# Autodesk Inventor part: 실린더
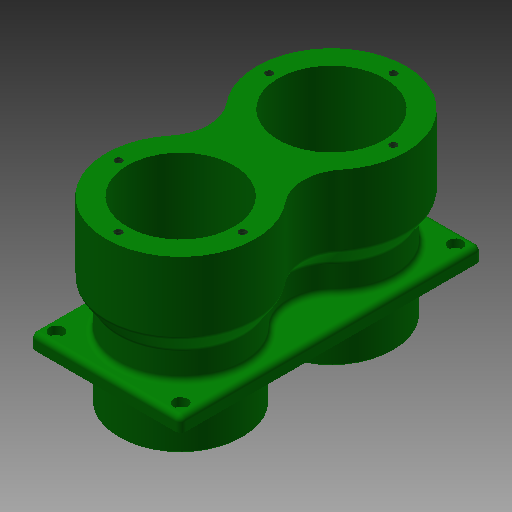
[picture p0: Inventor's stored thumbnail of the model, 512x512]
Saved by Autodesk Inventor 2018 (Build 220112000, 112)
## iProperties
Created: 2016-11
Part Number: 실린더
Material: 알루미늄 6061
Document SubType Name: Modeling
Designer: mduedu
Density: 2.71 g/cm^3
Mass: 1199.25 g
Surface Area: 1038.68 cm^2
Volume: 442.528 cm^3
Appearance: 진녹색
Author: mduedu
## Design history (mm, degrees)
sketch "스케치1"
  geometry: L1 (0, 0)-(0, 101); L2 (30, 0)-(30, 101); L3 (30, 101)-(42, 101); L4 (42, 101)-(42, 61); L5 (42, 61)-(35, 51); L6 (35, 51)-(35, 0); L7 (35, 0)-(30, 0)
  constraints: 14 end point, 4 parallel, 2 horizontal alignment, 1 perpendicular, 1 vertical
  dimensions: "d0" = 101 distance of L1.start L1.end; "d1" = 60 diameter of L2.end L1; "d2" = 84 diameter of L3.end L1; "d3" = 70 diameter of L6.end L1; "d4" = 40 distance of L3.end L4.end; "d5" = 50 vertical distance of L5.end L3.end
revolve "회전1" stored, may be unused: angle "d6" = 90 deg
node "작업 평면1"
sketch "스케치2"
  geometry: L1 (-42.5, -42.5)-(42.5, -42.5); L2 (42.5, -42.5)-(42.5, 42.5); L3 (42.5, 42.5)-(-42.5, 42.5); L4 (-42.5, 42.5)-(-42.5, -42.5); L5 (-42.5, -42.5)-(42.5, 42.5); L6 (42.5, -42.5)-(-42.5, 42.5); C1 r 35 at (0, 0) reference; C2 r 35 at (0, 0); 1 further point
  constraints: 12 end point, 2 midpoint, 2 parallel, 2 perpendicular, 1 centre point, 1 coincident, 1 concentric, 1 horizontal
  dimensions: "d8" = 85 distance of L2.end L3.end
extrude "돌출1" join sketch "스케치2" distance "d10" = 8; taper "d11" = 0 deg
chamfer "모따기1" distance "d14" = 1; stored, may be unused: second distance "d15" = 2, angle "d16" = 45 deg
chamfer "모따기2" distance "d17" = 5; stored, may be unused: second distance "d18" = 2, angle "d19" = 15 deg
sketch "스케치3"
  geometry: L1 (-35, -35)-(35, -35); L2 (35, -35)-(35, 35); L3 (35, 35)-(-35, 35); L4 (-35, 35)-(-35, -35); L5 (-35, -35)-(35, 35); L6 (35, -35)-(-35, 35); 3 further points
  constraints: 12 end point, 2 coincident, 2 midpoint, 2 parallel, 1 horizontal, 1 perpendicular
  dimensions: "d20" = 70 distance of L3.end L2.end; "d21" = 70 distance of L2.end L1.end
sketch "스케치4"
  geometry: 2 further points
  constraints: 2 other
hole "구멍1" sketch "스케치4" at (-35, 35), (35, 35) diameter "d22" = 4.5; stored, may be unused: countersink angle "d26" = 90 deg, drill point angle "d28" = 0 deg; dims "d23" = 6, "d24" = 8, "d25" = 4.6, "d27" = 8
sketch "스케치5"
  geometry: 3 further points
  constraints: 3 other
hole "구멍2" sketch "스케치5" at (35, 0), (-35, 0), (0, 35) diameter "d29" = 4.134; stored, may be unused: countersink angle "d33" = 90 deg, drill point angle "d35" = 120 deg; dims "d30" = 7.5, "d31" = 4, "d32" = 2, "d34" = 10
fillet "모깎기3" dims "d36" = 3
fillet "모깎기4" dims "d37" = 3
sketch "스케치6"
  geometry: L1 (0, 0)-(0, -85); A1 r 42 centre (0, 0) between (32.469, -26.642) and (-32.469, -26.642) reference; A2 r 42 centre (0, -85) between (32.469, -58.358) and (-32.469, -58.358) reference; A3 r 25 centre (51.795, -42.5) between (32.469, -58.358) and (32.469, -26.642); A4 r 25 centre (-51.795, -42.5) between (-32.469, -26.642) and (-32.469, -58.358); A5 r 25 centre (51.795, -42.5) between (32.469, -26.642) and (32.469, -58.358); A6 r 25 centre (-51.795, -42.5) between (-32.469, -58.358) and (-32.469, -26.642); A7 r 42 centre (0, 0) between (-32.469, -26.642) and (32.469, -26.642); A8 r 42 centre (0, -85) between (32.469, -58.358) and (-32.469, -58.358); A9 r 42 centre (0, 0) between (32.469, -26.642) and (-32.469, -26.642); A10 r 42 centre (0, -85) between (-32.469, -58.358) and (32.469, -58.358); 1 further point
  constraints: 20 point on circle, 8 centre point, 2 coincident, 2 end point, 2 tangent, 1 symmetric about line, 1 vertical, 1 other
  dimensions: "d38" = 50 diameter of A3
node "작업 평면2"
sketch "스케치7"
  geometry: A1 r 25 centre (9.795, -42.5) between (-9.531, -26.642) and (-9.531, -58.358) reference; A2 r 42 centre (-42, 0) between (-74.469, -26.642) and (-9.531, -26.642) reference; A3 r 42 centre (-42, -85) between (-9.531, -58.358) and (-74.469, -58.358) reference; A4 r 25 centre (-93.795, -42.5) between (-74.469, -58.358) and (-74.469, -26.642) reference; 1 further point
node "작업 평면3"
sketch "스케치8"
  geometry: L1 (-35, 0)-(-35, -85); A1 r 35 centre (-35, 0) between (-10.294, -24.792) and (-59.706, -24.792) reference; A2 r 35 centre (-35, -85) between (-10.294, -60.208) and (-59.706, -60.208) reference; A3 r 25 centre (7.353, -42.5) between (-10.294, -60.208) and (-10.294, -24.792); A4 r 25 centre (-77.353, -42.5) between (-59.706, -24.792) and (-59.706, -60.208); A5 r 25 centre (7.353, -42.5) between (-10.294, -24.792) and (-10.294, -60.208); A6 r 25 centre (-77.353, -42.5) between (-59.706, -60.208) and (-59.706, -24.792); A7 r 35 centre (-35, 0) between (-59.706, -24.792) and (-10.294, -24.792); A8 r 35 centre (-35, -85) between (-10.294, -60.208) and (-59.706, -60.208); 1 further point
  constraints: 16 point on circle, 6 centre point, 2 coincident, 2 end point, 2 tangent, 1 symmetric about line, 1 vertical, 1 other
  dimensions: "d40" = 50 diameter of A3
sketch "스케치9"
  geometry: A1 r 25 centre (42.353, -42.5) between (24.706, -24.792) and (24.706, -60.208) reference; A2 r 35 centre (0, 0) between (-24.706, -24.792) and (24.706, -24.792) reference; A3 r 35 centre (0, -85) between (24.706, -60.208) and (-24.706, -60.208) reference; A4 r 25 centre (-42.353, -42.5) between (-24.706, -60.208) and (-24.706, -24.792) reference; 1 further point
feature "로프트1" sketch "스케치8", "스케치9" dims "d42" = 0, "d43" = 90 deg, "d44" = 0, "d45" = 90 deg
feature "로프트2" dims "d46" = 0, "d47" = 90 deg, "d48" = 0, "d49" = 90 deg
  node "모서리1"
feature "로프트3" dims "d50" = 0, "d51" = 90 deg, "d52" = 0, "d53" = 90 deg
  node "모서리2"
fillet "모깎기5" dims "d54" = 3
node "솔리드1"
mirror "대칭1"
other parameters: "d7" = -27
